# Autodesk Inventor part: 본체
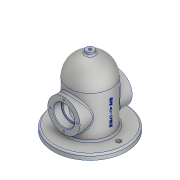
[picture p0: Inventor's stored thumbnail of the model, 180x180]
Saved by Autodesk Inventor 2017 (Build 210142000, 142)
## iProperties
Created: 2019-11
Part Number: 본체
Material: Aluminum 6061
Document SubType Name: Modeling
Designer: 1-06-lg
Density: 2.7 g/cm^3
Appearance: Aluminum - Flat
Mass: 1105.97 g
Surface Area: 883.573 cm^2
Volume: 409.619 cm^3
Author: 1-06-lg
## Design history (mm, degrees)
sketch "Sketch5"
  geometry: L1 (0, 0)-(90, 0); L2 (90, 0)-(90, -40); L3 (90, -40)-(0, -40); L4 (0, -40)-(0, 0); L5 (90, 0)-(130, 0); A1 r 40 centre (90, 0) between (50, 0) and (130, 0)
  constraints: 10 end point, 2 horizontal, 2 parallel, 2 point on circle, 1 centre point, 1 perpendicular, 1 point on line
  dimensions: "d6" = 80 diameter of L3 L1; "d7" = 90 distance of L1.start L1.end; "d8" = 80 diameter of A1
revolve "Revolution2" sketch "Sketch5" stored, may be unused: angle "d9" = 90 deg
sketch "Sketch6"
  geometry: C1 r 70 at (0, 0); 1 further point
  constraints: 1 centre point, 1 coincident
  dimensions: "d10" = 140 diameter of C1
extrude "Extrusion1" join sketch "Sketch6" distance "d11" = 10; taper "d12" = 0 deg
sketch "Sketch7"
  geometry: L1 (0, 0)-(0, 50); C1 r 31 at (0, 50)
  constraints: 2 end point, 1 centre point, 1 coincident, 1 vertical
  dimensions: "d13" = 50 distance of L1.start L1.end; "d14" = 62 diameter of C1
extrude "Extrusion2" join sketch "Sketch7" stored distance "d15" = 100; taper "d16" = 0 deg
sketch "Sketch8"
  geometry: L1 (0, 0)-(90, 0); L2 (90, 0)-(90, -30); L3 (90, -30)-(0, -30); L4 (0, -30)-(0, 0); L5 (90, 0)-(120, 0); A1 r 30 centre (90, 0) between (60, 0) and (120, 0)
  constraints: 10 end point, 2 horizontal, 2 parallel, 2 point on circle, 1 centre point, 1 perpendicular, 1 point on line
  dimensions: "d17" = 60 diameter of L3 L1; "d18" = 90 distance of L1.start L1.end; "d19" = 60 diameter of A1
revolve "Revolution3" sketch "Sketch8" stored, may be unused: angle "d20" = 90 deg
sketch "Sketch9"
  geometry: C1 r 31 at (0, 0) reference; C2 r 20 at (0, 0); 1 further point
  constraints: 1 centre point, 1 coincident
  dimensions: "d21" = 40 diameter of C2
extrude "Extrusion3" cut sketch "Sketch9" distance "d22" = 15; taper "d23" = 0 deg
sketch "Sketch10"
  geometry: C1 r 20 at (0, 0) reference; C2 r 16.5 at (0, 0); 1 further point
  constraints: 1 centre point, 1 coincident
  dimensions: "d24" = 33 diameter of C2
extrude "Extrusion4" cut sketch "Sketch10" stored distance "d25" = 15; taper "d26" = 0 deg
sketch "Sketch11" dims "d27" = 52
  geometry: L1 (0, 0)-(0, 26); C1 r 31 at (0, 0) reference; 2 further points
  constraints: 2 coincident, 2 end point, 1 vertical, 1 vertical alignment, 2 other
hole "Hole1" sketch "Sketch11" at (0, 26) diameter "d28" = 3.242; stored, may be unused: countersink angle "d32" = 90 deg, drill point angle "d34" = 118 deg; dims "d29" = 8, "d30" = 4, "d31" = 2, "d33" = 10
pattern_circular "Circular Pattern1" dims angle "d36" = 360 deg
mirror "Mirror2"
workplane "Work Plane1"
sketch "Sketch12"
  geometry: C1 r 7.5 at (0, 0); 1 further point
  constraints: 1 centre point, 1 coincident
  dimensions: "d39" = 15 diameter of C1
extrude "Extrusion5" join sketch "Sketch12" stored distance "d40" = 15; taper "d41" = 0 deg
sketch "Sketch13"
  geometry: C1 r 7.5 at (0, 0) reference; 1 further point
  constraints: 1 coincident
hole "Hole2" sketch "Sketch13" at (0, 0) diameter "d42" = 5.188; stored, may be unused: countersink angle "d46" = 90 deg, drill point angle "d48" = 118 deg; dims "d43" = 12, "d44" = 4, "d45" = 2, "d47" = 16
sketch "Sketch14" dims "d49" = 110
  geometry: L1 (0, 0)-(55, 0); C1 r 40 at (0, 0) reference; C2 r 4.5 at (55, 0)
  constraints: 2 coincident, 2 end point, 1 centre point, 1 horizontal, 1 horizontal alignment, 2 other
  dimensions: "d50" = 9 diameter of C2
extrude "Extrusion6" cut sketch "Sketch14" stored distance "d51" = 15; taper "d52" = 0 deg
pattern_circular "Circular Pattern2" dims angle "d54" = 360 deg
workplane "Work Plane2"
sketch "Sketch15"
  geometry: L1 (0, 70)-(0, -70) reference; L2 (0, 70)-(10, 70) reference; 2 further points
  constraints: 1 other
  dimensions: "d57" = 50 distance from line of L1 point (50, 0)
emboss "Emboss1" sketch "Sketch15" dims "d6" = 80, "d7" = 90, "d8" = 80, "d17" = 60, "d18" = 90, "d19" = 60, "d59" = 0.5, "d60" = 0
fillet "Fillet1" dims "d61" = 3
chamfer "Chamfer1" distance "d62" = 1; stored, may be unused: second distance "d63" = 2, angle "d64" = 45 deg
fillet "Fillet2" dims "d65" = 0.3
fillet "Fillet3" dims "d66" = 3
fillet "Fillet4" dims "d67" = 3
body "Solid2"
other parameters: "d38" = 135
